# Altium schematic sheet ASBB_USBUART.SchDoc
size A4
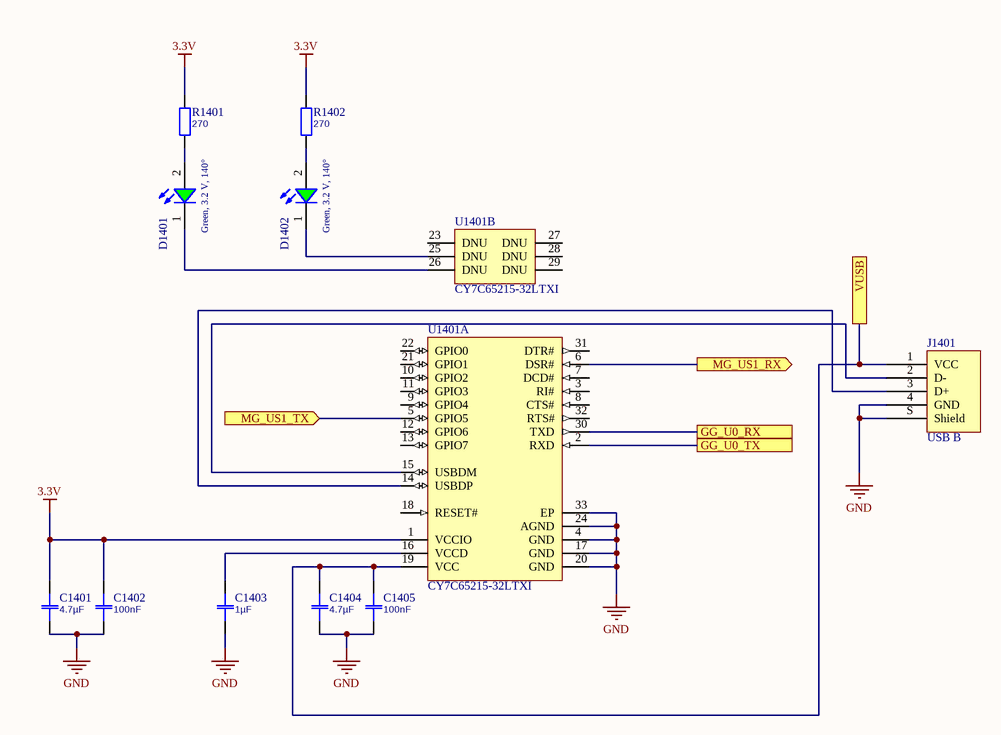
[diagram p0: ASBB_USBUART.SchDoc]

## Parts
C1401  4.7µF  [0603]
C1402  100nF  [0603]
C1403  1µF  [0603]
C1404  4.7µF  [0603]
C1405  100nF  [0603]
D1401  Green, 3.2 V, 140°  [WL-SMCW_0603]
D1402  Green, 3.2 V, 140°  [WL-SMCW_0603]
J1401  USB B  [FCI USB 10118193-0001LF]
R1401  270  [0603]
R1402  270  [0603]
U1401  CY7C65215-32LTXI  [CYP-LTX32_N]  (parts A,B of 2)

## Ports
GG_U0_RX, GG_U0_TX, MG_US1_RX (out), MG_US1_TX (in), VUSB

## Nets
3.3V: C1401.2 C1402.2 R1401.2 R1402.2 U1401.1(VCCIO)
GND: C1401.1 C1402.1 C1403.1 C1404.1 C1405.1 J1401.4(GND) J1401.S(Shield) U1401.4(GND) U1401.17(GND) U1401.20(GND) U1401.24(AGND) U1401.33(EP)
GG_U0_RX: U1401.30(TXD) ; port GG_U0_RX
GG_U0_TX: U1401.2(RXD) ; port GG_U0_TX
MG_US1_RX: U1401.6(DSR#) ; port MG_US1_RX
MG_US1_TX: U1401.5(GPIO5) ; port MG_US1_TX
VUSB: C1404.2 C1405.2 J1401.1(VCC) U1401.19(VCC) ; port VUSB
NetC1403_2: C1403.2 U1401.16(VCCD)
NetD1401_1: D1401.1(K) U1401.26(DNU)
NetD1401_2: D1401.2(A) R1401.1
NetD1402_1: D1402.1(K) U1401.25(DNU)
NetD1402_2: D1402.2(A) R1402.1
NetJ1401_2: J1401.2(D-) U1401.15(USBDM)
NetJ1401_3: J1401.3(D+) U1401.14(USBDP)

Not connected (* = marked no-connect by the designer): U1401 3(RI#) 7(DCD#) 8(CTS#) 9(GPIO4) 10(GPIO2) 11(GPIO3) 12(GPIO6) 13(GPIO7) 18(RESET#) 21(GPIO1) 22(GPIO0) 23(DNU) 27(DNU) 28(DNU) 29(DNU) 31(DTR#) 32(RTS#)

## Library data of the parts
C1401-C1405 = Capacitor
D1401 D1402 = 150060GS75000: WL-SMCW SMD Mono-color Chip LED Waterclear, size 0603, Green, 3.2 V, 140°; Forward Voltage: 3.2 V; Peak Wavelength: 515 nm; Dominant Wavelength: 525 nm; Luminous Intensity: 430 mcd
J1401 = USB 2.0 Type B
R1401 R1402 = Resistor
U1401 = CY7C65215-32LTXI: USB-Serial Dual Channel (UART/I2C/SPI) Bridge with CapSense(R) and BCD, 0.5 KB, 19 I/Os, 1.71 to 5.5 V, -40 to 85 degC, 32-Pin QFN (LTX32), Tray; Manufacturer: Cypress; CPU Core: M8; Max. Operating Voltage (V): 5.5; Memory Architecture: Flash; Memory Size (KB): 0.5; Min. Operating Voltage (V): 1.71; No. of I/Os: 19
